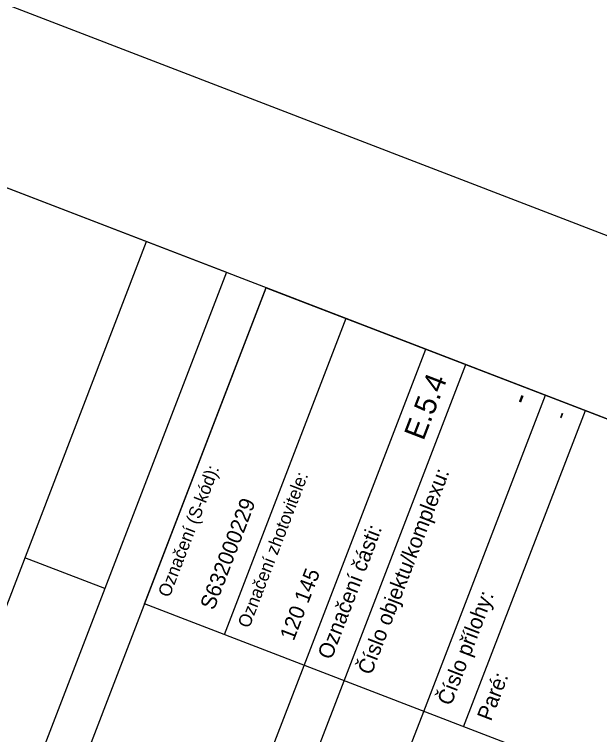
# Model space of a CAD drawing. Extents: x -755061 to -754557, y -1162352 to -1161657.
# Drawn here: x -754684.5 to -754616, y -1161799.7 to -1161715.4 of the extents above; entities that cross this region are included whole.
import ezdxf

# ---------------------------------------------------------------- set-up
doc = ezdxf.new("R2010")
doc.units = 0
doc.layers.add('Formát', color=7, linetype='Continuous')
doc.layers.add('Popisove_pole', color=7, linetype='Continuous')

msp = doc.modelspace()

# ---------------------------------------------------------------- linework, layer by layer
at = {"layer": 'Formát'}
for p, q in [((-754730.056, -1161900.651), (-754668.997, -1161741.995)), ((-754659.907, -1161787.979), (-754645.665, -1161750.974)), ((-754650.574, -1161791.57), (-754636.333, -1161754.566)), ((-754645.907, -1161793.366), (-754631.666, -1161756.362)), ((-754636.575, -1161796.958), (-754622.334, -1161759.954)), ((-754631.908, -1161798.754), (-754617.667, -1161761.749)), ((-754673.906, -1161782.591), (-754683.238, -1161778.999)), ((-754697.392, -1161913.222), (-754650.574, -1161791.57)), ((-754692.725, -1161915.018), (-754645.907, -1161793.366)), ((-754683.393, -1161918.61), (-754636.575, -1161796.958))]:
    msp.add_line(p, q, dxfattribs=at)
msp.add_lwpolyline([(-754909.895, -1161852.87), (-754834.469, -1161656.883), (-754557.287, -1161763.557), (-754632.713, -1161959.544)], dxfattribs=at)
for points in [[(-754884.046, -1161841.388), (-754822.987, -1161682.732), (-754580.336, -1161776.116), (-754641.396, -1161934.773)], [(-754767.387, -1161886.284), (-754706.328, -1161727.628), (-754659.664, -1161745.587), (-754720.724, -1161904.243)], [(-754716.062, -1161906.051), (-754655.003, -1161747.395), (-754589.674, -1161772.537), (-754650.733, -1161931.193)], [(-754589.669, -1161772.525), (-754603.91, -1161809.529), (-754669.239, -1161784.387), (-754654.998, -1161747.383)]]:
    msp.add_lwpolyline(points, close=True, dxfattribs=at)

# ---------------------------------------------------------------- texts
for s, height, p in [('-', 2.5, (-754624.467, -1161761.257)), ('-', 1.8, (-754619.937, -1161762.975)), ('Označení (S-kód):', 1.5, (-754666.326, -1161783.713)), ('Číslo objektu/komplexu:', 1.8, (-754642.715, -1161792.8)), ('Označení zhotovitele:', 1.5, (-754656.994, -1161787.305)), ('S632000229', 1.8, (-754661.129, -1161785.208)), ('Označení části:', 1.8, (-754647.381, -1161791.004)), ('120 145', 1.8, (-754651.796, -1161788.799)), ('Číslo přílohy:', 1.8, (-754633.382, -1161796.392)), ('Paré:', 1.8, (-754628.715, -1161798.188))]:
    msp.add_text(s, height=height, rotation=68.95068, dxfattribs=at).set_placement(p)
at = {"layer": 'Popisove_pole'}
msp.add_text('E.5.4', height=2.5, rotation=68.9507, dxfattribs=at).set_placement((-754636.616, -1161765.378))

doc.saveas('drawing.dxf')
